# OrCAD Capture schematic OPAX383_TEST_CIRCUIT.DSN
size A; title: OPAx383 5.5V Precision, Chopper Op Amp; rev: 1.0; note: Datasheet: SBOSAK7 - DEC "24  EVM: N/A
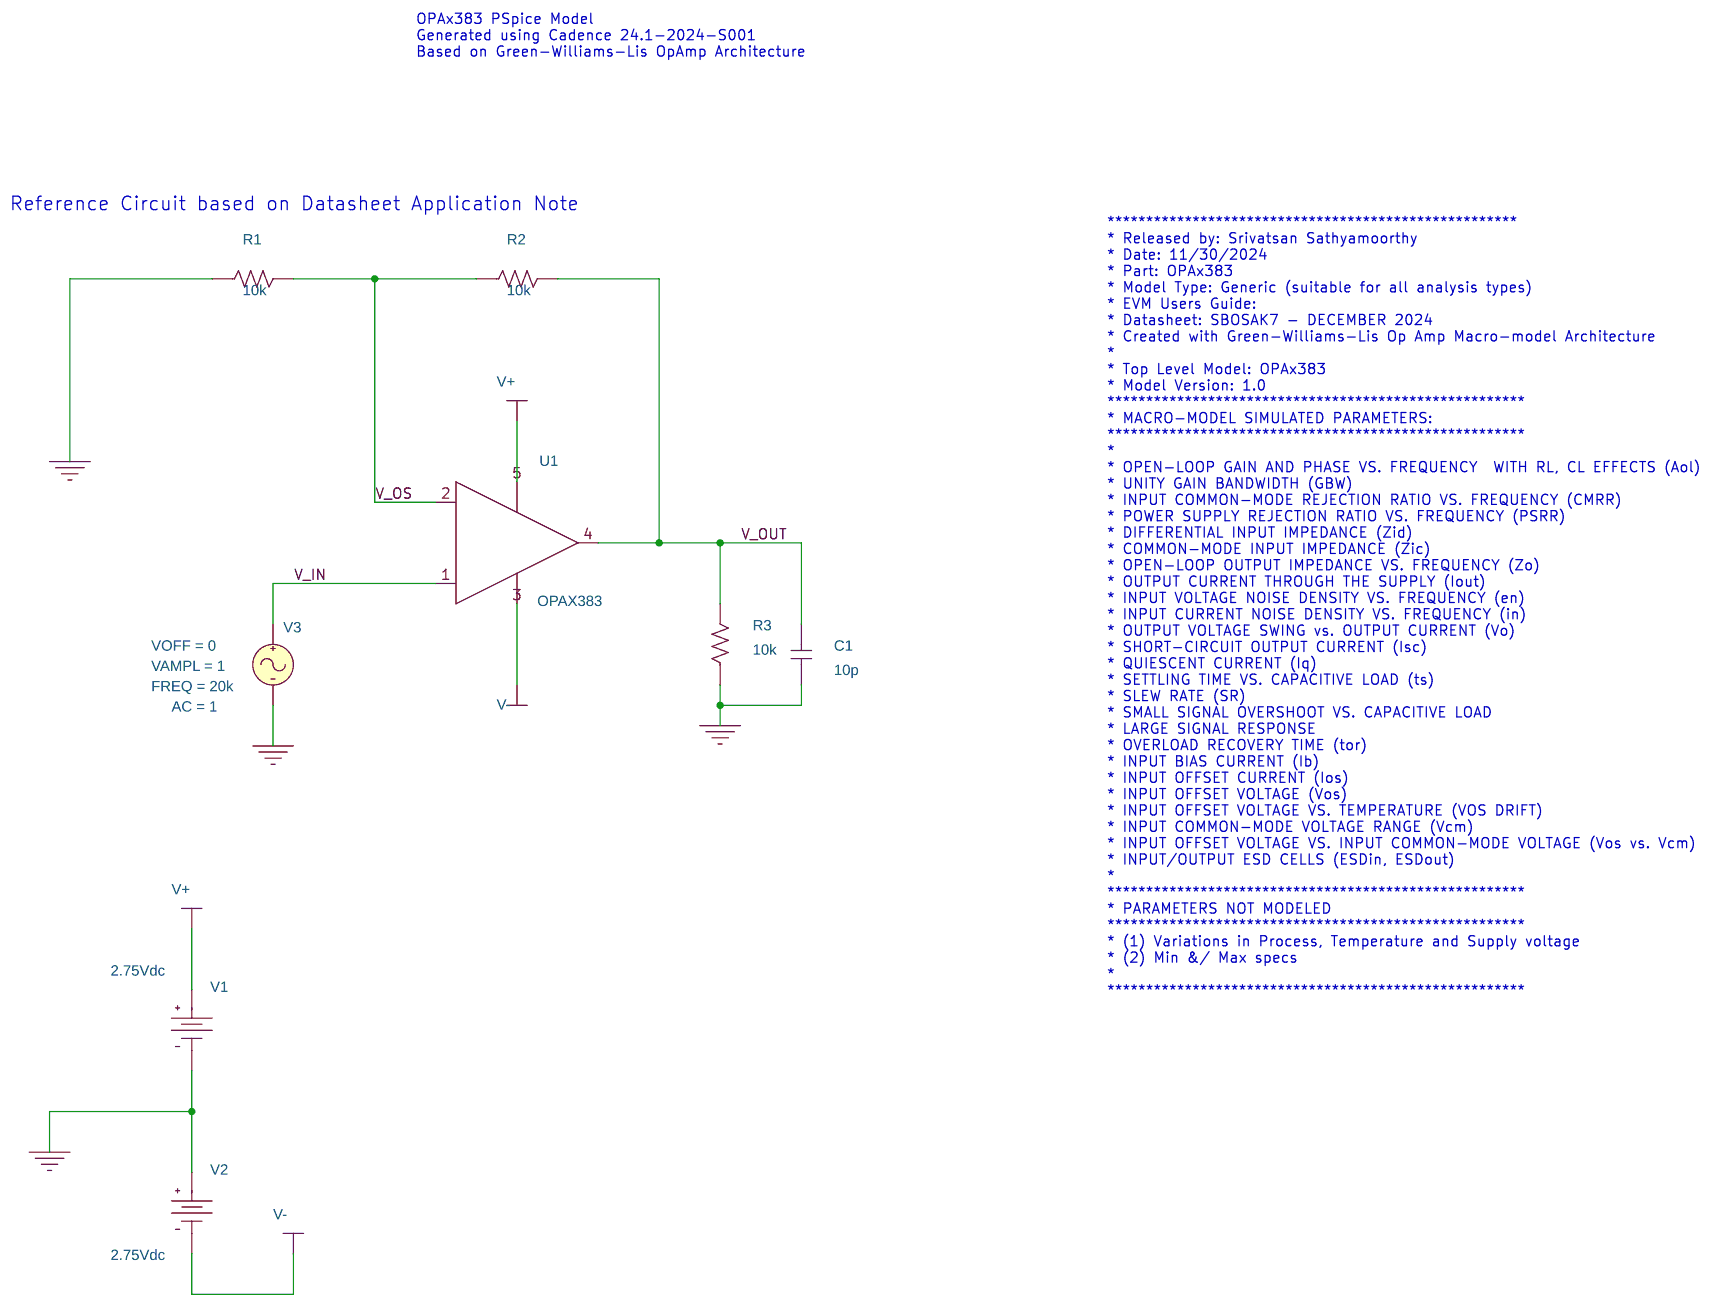
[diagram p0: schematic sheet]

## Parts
C1  10p  [cap196]
R1  10k  [AXRC05]
R2  10k  [AXRC05]
R3  10k  [AXRC05]
U1  OPAX383
V1  VDC
V2  VDC
V3  VSIN

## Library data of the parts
C1 = C
R1-R3 = R
U1 = OPAX383
V1 V2 = VDC: DC: 2.75Vdc
V3 = VSIN: AC: 1; AppProp: Sine$Voltage$0$-1; DC: 0; FREQ: 20k; TD: 10u; VAMPL: 1; VOFF: 0

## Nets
0: C1.1 R1.1 R3.1 V1.1(-) V2.0(+) V3.2(-)
V+: U1.5(V+) V1.0(+)
V-: U1.3(V-) V2.1(-)
V_IN: U1.1(+) V3.1(+)
V_OS: R1.2 R2.1 U1.2(-)
V_OUT: C1.2 R2.2 R3.2 U1.4(OUT)

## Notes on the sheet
- OPAx383 PSpice Model
  Generated using Cadence 24.1-2024-S001
  Based on Green-Williams-Lis OpAmp Architecture
- Reference Circuit based on Datasheet Application Note
- *****************************************************
  * Released by: Srivatsan Sathyamoorthy
  * Date: 11/30/2024
  * Part: OPAx383
  * Model Type: Generic (suitable for all analysis types)
  * EVM Users Guide:
  * Datasheet: SBOSAK7 - DECEMBER 2024
  * Created with Green-Williams-Lis Op Amp Macro-model Architecture
  *
  * Top Level Model: OPAx383
  * Model Version: 1.0
  ******************************************************
  * MACRO-MODEL SIMULATED PARAMETERS:
  ******************************************************
  *
  * OPEN-LOOP GAIN AND PHASE VS. FREQUENCY  WITH RL, CL EFFECTS (Aol)
  * UNITY GAIN BANDWIDTH (GBW)
  * INPUT COMMON-MODE REJECTION RATIO VS. FREQUENCY (CMRR)
  * POWER SUPPLY REJECTION RATIO VS. FREQUENCY (PSRR)
  * DIFFERENTIAL INPUT IMPEDANCE (Zid)
  * COMMON-MODE INPUT IMPEDANCE (Zic)
  * OPEN-LOOP OUTPUT IMPEDANCE VS. FREQUENCY (Zo)
  * OUTPUT CURRENT THROUGH THE SUPPLY (Iout)
  * INPUT VOLTAGE NOISE DENSITY VS. FREQUENCY (en)
  * INPUT CURRENT NOISE DENSITY VS. FREQUENCY (in)
  * OUTPUT VOLTAGE SWING vs. OUTPUT CURRENT (Vo)
  * SHORT-CIRCUIT OUTPUT CURRENT (Isc)
  * QUIESCENT CURRENT (Iq)
  * SETTLING TIME VS. CAPACITIVE LOAD (ts)
  * SLEW RATE (SR)
  * SMALL SIGNAL OVERSHOOT VS. CAPACITIVE LOAD
  * LARGE SIGNAL RESPONSE
  * OVERLOAD RECOVERY TIME (tor)
  * INPUT BIAS CURRENT (Ib)
  * INPUT OFFSET CURRENT (Ios)
  * INPUT OFFSET VOLTAGE (Vos)
  * INPUT OFFSET VOLTAGE VS. TEMPERATURE (VOS DRIFT)
  * INPUT COMMON-MODE VOLTAGE RANGE (Vcm)
  * INPUT OFFSET VOLTAGE VS. INPUT COMMON-MODE VOLTAGE (Vos vs. Vcm)
  * INPUT/OUTPUT ESD CELLS (ESDin, ESDout)
  *
  ******************************************************
  * PARAMETERS NOT MODELED
  ******************************************************
  * (1) Variations in Process, Temperature and Supply voltage
  * (2) Min &/ Max specs
  *
  ******************************************************
